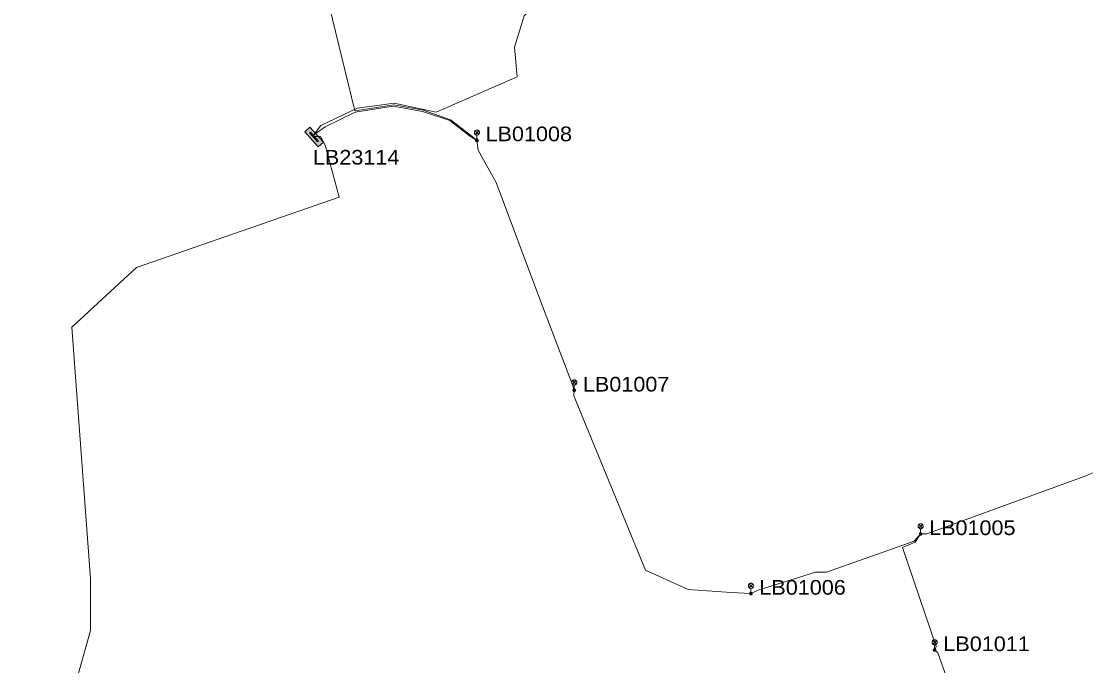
# Model space of a CAD drawing. Extents: x -688049 to -687261, y -973611 to -973038.
# Drawn here: x -687423.8 to -687265.6, y -973324.5 to -973229.3 of the extents above; entities that cross this region are included whole.
import ezdxf

# ---------------------------------------------------------------- set-up
doc = ezdxf.new("R2010")
doc.units = 0
doc.header["$LTSCALE"] = 0.87
doc.layers.add('1', color=7, linetype='Continuous', lineweight=13)

msp = doc.modelspace()

# ---------------------------------------------------------------- hatches: boundary and pattern name
at = {"layer": '1'}
for points in [[(-687379.952, -973247.823), (-687381.968, -973245.601), (-687381.227, -973244.929), (-687379.211, -973247.151)], [(-687380.059, -973247.109), (-687381.268, -973245.776), (-687381.12, -973245.642), (-687379.911, -973246.975)]]:
    msp.add_hatch(color=256, dxfattribs=at).paths.add_polyline_path(points)

# ---------------------------------------------------------------- linework, layer by layer
for p, q in [((-687356.805, -973245.455), (-687356.275, -973245.985)), ((-687356.805, -973245.985), (-687356.275, -973245.455)), ((-687356.54, -973246.87), (-687356.54, -973246.095)), ((-687342.425, -973282.375), (-687341.895, -973282.905)), ((-687342.425, -973282.905), (-687341.895, -973282.375)), ((-687291.275, -973303.625), (-687290.745, -973304.155)), ((-687291.275, -973304.155), (-687290.745, -973303.625)), ((-687291.01, -973305.04), (-687291.01, -973304.265)), ((-687316.335, -973312.435), (-687315.805, -973312.965)), ((-687316.335, -973312.965), (-687315.805, -973312.435)), ((-687289.215, -973320.775), (-687288.685, -973321.305)), ((-687289.215, -973321.305), (-687288.685, -973320.775)), ((-687288.95, -973322.19), (-687288.95, -973321.415))]:
    msp.add_line(p, q, dxfattribs=at)
for points in [[(-687356.54, -973246.87), (-687357.499, -973246.115), (-687360.447, -973243.857), (-687364.449, -973242.409), (-687368.798, -973241.637), (-687374.546, -973242.515), (-687382.562, -973209.507), (-687381.261, -973209.073), (-687380.24, -973207.97), (-687379.671, -973205.153), (-687381.293, -973203.137), (-687381.75, -973202.33)], [(-687350.83, -973213.5), (-687350.83, -973214.75), (-687347.414, -973226.104), (-687349.576, -973228.47), (-687350.998, -973233.095), (-687350.592, -973237.466), (-687362.557, -973242.691), (-687368.775, -973241.359), (-687374.206, -973242.131), (-687379.571, -973244.67), (-687380.798, -973246.294)], [(-687356.54, -973246.87), (-687357.651, -973246.213), (-687360.537, -973243.936), (-687364.573, -973242.598), (-687368.892, -973241.832), (-687374.497, -973242.717), (-687378.935, -973244.864), (-687380.483, -973245.949), (-687380.798, -973246.294)], [(-687380.798, -973246.294), (-687379.608, -973246.294), (-687378.955, -973247.562), (-687376.887, -973255.287), (-687406.818, -973265.671), (-687416.352, -973274.485), (-687413.576, -973311.675), (-687413.576, -973319.312), (-687415.981, -973327.719), (-687423.796, -973339.13), (-687419.572, -973351.385), (-687409.434, -973351.385), (-687402.464, -973355.4), (-687399.787, -973359.445), (-687396.201, -973367.518), (-687384.836, -973404.179), (-687376.008, -973424.395), (-687374.353, -973427.776), (-687369.362, -973427.776), (-687366.818, -973426.737), (-687366.538, -973425.138)], [(-687356.54, -973246.87), (-687356.347, -973248.305), (-687355.541, -973249.752), (-687353.676, -973253.1), (-687347.241, -973270.349), (-687342.401, -973283), (-687342.16, -973283.79), (-687342.16, -973283.015)], [(-687342.16, -973283.79), (-687342.227, -973284.618), (-687331.633, -973310.364), (-687325.353, -973313.26), (-687318.994, -973313.706), (-687316.07, -973313.85), (-687316.07, -973313.075)], [(-687291.01, -973305.04), (-687290.095, -973305.04), (-687266.448, -973296.412), (-687265.62, -973296)], [(-687316.07, -973313.85), (-687315.003, -973313.354), (-687306.515, -973310.665), (-687304.901, -973310.665), (-687291.976, -973306.105), (-687291.01, -973305.04)], [(-687291.01, -973305.04), (-687291.832, -973306.235), (-687293.694, -973307.029), (-687288.717, -973321.646), (-687288.9, -973322.19)], [(-687288.9, -973322.19), (-687288.451, -973322.592), (-687278.691, -973350.089), (-687278.75, -973350.656)]]:
    msp.add_lwpolyline(points, dxfattribs=at)
for points in [[(-687379.952, -973247.823), (-687381.968, -973245.601), (-687381.227, -973244.929), (-687379.211, -973247.151)], [(-687379.952, -973247.823), (-687381.968, -973245.601), (-687381.227, -973244.929), (-687379.211, -973247.151)], [(-687380.059, -973247.109), (-687381.268, -973245.776), (-687381.12, -973245.642), (-687379.911, -973246.975)], [(-687356.165, -973245.72), (-687356.171, -973245.655), (-687356.188, -973245.592), (-687356.215, -973245.533), (-687356.253, -973245.479), (-687356.299, -973245.433), (-687356.352, -973245.395), (-687356.412, -973245.368), (-687356.475, -973245.351), (-687356.54, -973245.345), (-687356.605, -973245.351), (-687356.668, -973245.368), (-687356.728, -973245.395), (-687356.781, -973245.433), (-687356.827, -973245.479), (-687356.865, -973245.533), (-687356.892, -973245.592), (-687356.909, -973245.655), (-687356.915, -973245.72), (-687356.909, -973245.785), (-687356.892, -973245.848), (-687356.865, -973245.908), (-687356.827, -973245.961), (-687356.781, -973246.007), (-687356.728, -973246.045), (-687356.668, -973246.072), (-687356.605, -973246.089), (-687356.54, -973246.095), (-687356.475, -973246.089), (-687356.412, -973246.072), (-687356.352, -973246.045), (-687356.299, -973246.007), (-687356.253, -973245.961), (-687356.215, -973245.908), (-687356.188, -973245.848), (-687356.171, -973245.785)], [(-687356.35, -973246.87), (-687356.353, -973246.837), (-687356.361, -973246.805), (-687356.375, -973246.775), (-687356.394, -973246.748), (-687356.418, -973246.724), (-687356.445, -973246.705), (-687356.475, -973246.691), (-687356.507, -973246.683), (-687356.54, -973246.68), (-687356.573, -973246.683), (-687356.605, -973246.691), (-687356.635, -973246.705), (-687356.662, -973246.724), (-687356.686, -973246.748), (-687356.705, -973246.775), (-687356.719, -973246.805), (-687356.727, -973246.837), (-687356.73, -973246.87), (-687356.727, -973246.903), (-687356.719, -973246.935), (-687356.705, -973246.965), (-687356.686, -973246.992), (-687356.662, -973247.016), (-687356.635, -973247.035), (-687356.605, -973247.049), (-687356.573, -973247.057), (-687356.54, -973247.06), (-687356.507, -973247.057), (-687356.475, -973247.049), (-687356.445, -973247.035), (-687356.418, -973247.016), (-687356.394, -973246.992), (-687356.375, -973246.965), (-687356.361, -973246.935), (-687356.353, -973246.903)], [(-687356.49, -973246.87), (-687356.491, -973246.861), (-687356.493, -973246.853), (-687356.497, -973246.845), (-687356.502, -973246.838), (-687356.508, -973246.832), (-687356.515, -973246.827), (-687356.523, -973246.823), (-687356.531, -973246.821), (-687356.54, -973246.82), (-687356.549, -973246.821), (-687356.557, -973246.823), (-687356.565, -973246.827), (-687356.572, -973246.832), (-687356.578, -973246.838), (-687356.583, -973246.845), (-687356.587, -973246.853), (-687356.589, -973246.861), (-687356.59, -973246.87), (-687356.589, -973246.879), (-687356.587, -973246.887), (-687356.583, -973246.895), (-687356.578, -973246.902), (-687356.572, -973246.908), (-687356.565, -973246.913), (-687356.557, -973246.917), (-687356.549, -973246.919), (-687356.54, -973246.92), (-687356.531, -973246.919), (-687356.523, -973246.917), (-687356.515, -973246.913), (-687356.508, -973246.908), (-687356.502, -973246.902), (-687356.497, -973246.895), (-687356.493, -973246.887), (-687356.491, -973246.879)], [(-687341.785, -973282.64), (-687341.791, -973282.575), (-687341.808, -973282.512), (-687341.835, -973282.452), (-687341.873, -973282.399), (-687341.919, -973282.353), (-687341.972, -973282.315), (-687342.032, -973282.288), (-687342.095, -973282.271), (-687342.16, -973282.265), (-687342.225, -973282.271), (-687342.288, -973282.288), (-687342.348, -973282.315), (-687342.401, -973282.353), (-687342.447, -973282.399), (-687342.485, -973282.452), (-687342.512, -973282.512), (-687342.529, -973282.575), (-687342.535, -973282.64), (-687342.529, -973282.705), (-687342.512, -973282.768), (-687342.485, -973282.828), (-687342.447, -973282.881), (-687342.401, -973282.927), (-687342.348, -973282.965), (-687342.288, -973282.992), (-687342.225, -973283.009), (-687342.16, -973283.015), (-687342.095, -973283.009), (-687342.032, -973282.992), (-687341.972, -973282.965), (-687341.919, -973282.927), (-687341.873, -973282.881), (-687341.835, -973282.828), (-687341.808, -973282.768), (-687341.791, -973282.705)], [(-687341.97, -973283.79), (-687341.973, -973283.757), (-687341.981, -973283.725), (-687341.995, -973283.695), (-687342.014, -973283.668), (-687342.038, -973283.644), (-687342.065, -973283.625), (-687342.095, -973283.611), (-687342.127, -973283.603), (-687342.16, -973283.6), (-687342.193, -973283.603), (-687342.225, -973283.611), (-687342.255, -973283.625), (-687342.282, -973283.644), (-687342.306, -973283.668), (-687342.325, -973283.695), (-687342.339, -973283.725), (-687342.347, -973283.757), (-687342.35, -973283.79), (-687342.347, -973283.823), (-687342.339, -973283.855), (-687342.325, -973283.885), (-687342.306, -973283.912), (-687342.282, -973283.936), (-687342.255, -973283.955), (-687342.225, -973283.969), (-687342.193, -973283.977), (-687342.16, -973283.98), (-687342.127, -973283.977), (-687342.095, -973283.969), (-687342.065, -973283.955), (-687342.038, -973283.936), (-687342.014, -973283.912), (-687341.995, -973283.885), (-687341.981, -973283.855), (-687341.973, -973283.823)], [(-687342.11, -973283.79), (-687342.111, -973283.781), (-687342.113, -973283.773), (-687342.117, -973283.765), (-687342.122, -973283.758), (-687342.128, -973283.752), (-687342.135, -973283.747), (-687342.143, -973283.743), (-687342.151, -973283.741), (-687342.16, -973283.74), (-687342.169, -973283.741), (-687342.177, -973283.743), (-687342.185, -973283.747), (-687342.192, -973283.752), (-687342.198, -973283.758), (-687342.203, -973283.765), (-687342.207, -973283.773), (-687342.209, -973283.781), (-687342.21, -973283.79), (-687342.209, -973283.799), (-687342.207, -973283.807), (-687342.203, -973283.815), (-687342.198, -973283.822), (-687342.192, -973283.828), (-687342.185, -973283.833), (-687342.177, -973283.837), (-687342.169, -973283.839), (-687342.16, -973283.84), (-687342.151, -973283.839), (-687342.143, -973283.837), (-687342.135, -973283.833), (-687342.128, -973283.828), (-687342.122, -973283.822), (-687342.117, -973283.815), (-687342.113, -973283.807), (-687342.111, -973283.799)], [(-687290.635, -973303.89), (-687290.641, -973303.825), (-687290.658, -973303.762), (-687290.685, -973303.702), (-687290.723, -973303.649), (-687290.769, -973303.603), (-687290.822, -973303.565), (-687290.882, -973303.538), (-687290.945, -973303.521), (-687291.01, -973303.515), (-687291.075, -973303.521), (-687291.138, -973303.538), (-687291.198, -973303.565), (-687291.251, -973303.603), (-687291.297, -973303.649), (-687291.335, -973303.702), (-687291.362, -973303.762), (-687291.379, -973303.825), (-687291.385, -973303.89), (-687291.379, -973303.955), (-687291.362, -973304.018), (-687291.335, -973304.078), (-687291.297, -973304.131), (-687291.251, -973304.177), (-687291.198, -973304.215), (-687291.138, -973304.242), (-687291.075, -973304.259), (-687291.01, -973304.265), (-687290.945, -973304.259), (-687290.882, -973304.242), (-687290.822, -973304.215), (-687290.769, -973304.177), (-687290.723, -973304.131), (-687290.685, -973304.078), (-687290.658, -973304.018), (-687290.641, -973303.955)], [(-687290.82, -973305.04), (-687290.823, -973305.007), (-687290.831, -973304.975), (-687290.845, -973304.945), (-687290.864, -973304.918), (-687290.888, -973304.894), (-687290.915, -973304.875), (-687290.945, -973304.861), (-687290.977, -973304.853), (-687291.01, -973304.85), (-687291.043, -973304.853), (-687291.075, -973304.861), (-687291.105, -973304.875), (-687291.132, -973304.894), (-687291.156, -973304.918), (-687291.175, -973304.945), (-687291.189, -973304.975), (-687291.197, -973305.007), (-687291.2, -973305.04), (-687291.197, -973305.073), (-687291.189, -973305.105), (-687291.175, -973305.135), (-687291.156, -973305.162), (-687291.132, -973305.186), (-687291.105, -973305.205), (-687291.075, -973305.219), (-687291.043, -973305.227), (-687291.01, -973305.23), (-687290.977, -973305.227), (-687290.945, -973305.219), (-687290.915, -973305.205), (-687290.888, -973305.186), (-687290.864, -973305.162), (-687290.845, -973305.135), (-687290.831, -973305.105), (-687290.823, -973305.073)], [(-687290.96, -973305.04), (-687290.961, -973305.031), (-687290.963, -973305.023), (-687290.967, -973305.015), (-687290.972, -973305.008), (-687290.978, -973305.002), (-687290.985, -973304.997), (-687290.993, -973304.993), (-687291.001, -973304.991), (-687291.01, -973304.99), (-687291.019, -973304.991), (-687291.027, -973304.993), (-687291.035, -973304.997), (-687291.042, -973305.002), (-687291.048, -973305.008), (-687291.053, -973305.015), (-687291.057, -973305.023), (-687291.059, -973305.031), (-687291.06, -973305.04), (-687291.059, -973305.049), (-687291.057, -973305.057), (-687291.053, -973305.065), (-687291.048, -973305.072), (-687291.042, -973305.078), (-687291.035, -973305.083), (-687291.027, -973305.087), (-687291.019, -973305.089), (-687291.01, -973305.09), (-687291.001, -973305.089), (-687290.993, -973305.087), (-687290.985, -973305.083), (-687290.978, -973305.078), (-687290.972, -973305.072), (-687290.967, -973305.065), (-687290.963, -973305.057), (-687290.961, -973305.049)], [(-687315.695, -973312.7), (-687315.701, -973312.635), (-687315.718, -973312.572), (-687315.745, -973312.513), (-687315.783, -973312.459), (-687315.829, -973312.413), (-687315.883, -973312.375), (-687315.942, -973312.348), (-687316.005, -973312.331), (-687316.07, -973312.325), (-687316.135, -973312.331), (-687316.198, -973312.348), (-687316.258, -973312.375), (-687316.311, -973312.413), (-687316.357, -973312.459), (-687316.395, -973312.513), (-687316.422, -973312.572), (-687316.439, -973312.635), (-687316.445, -973312.7), (-687316.439, -973312.765), (-687316.422, -973312.828), (-687316.395, -973312.888), (-687316.357, -973312.941), (-687316.311, -973312.987), (-687316.258, -973313.025), (-687316.198, -973313.052), (-687316.135, -973313.069), (-687316.07, -973313.075), (-687316.005, -973313.069), (-687315.942, -973313.052), (-687315.883, -973313.025), (-687315.829, -973312.987), (-687315.783, -973312.941), (-687315.745, -973312.888), (-687315.718, -973312.828), (-687315.701, -973312.765)], [(-687315.88, -973313.85), (-687315.883, -973313.817), (-687315.891, -973313.785), (-687315.905, -973313.755), (-687315.924, -973313.728), (-687315.948, -973313.704), (-687315.975, -973313.685), (-687316.005, -973313.671), (-687316.037, -973313.663), (-687316.07, -973313.66), (-687316.103, -973313.663), (-687316.135, -973313.671), (-687316.165, -973313.685), (-687316.192, -973313.704), (-687316.216, -973313.728), (-687316.235, -973313.755), (-687316.249, -973313.785), (-687316.257, -973313.817), (-687316.26, -973313.85), (-687316.257, -973313.883), (-687316.249, -973313.915), (-687316.235, -973313.945), (-687316.216, -973313.972), (-687316.192, -973313.996), (-687316.165, -973314.015), (-687316.135, -973314.029), (-687316.103, -973314.037), (-687316.07, -973314.04), (-687316.037, -973314.037), (-687316.005, -973314.029), (-687315.975, -973314.015), (-687315.948, -973313.996), (-687315.924, -973313.972), (-687315.905, -973313.945), (-687315.891, -973313.915), (-687315.883, -973313.883)], [(-687316.02, -973313.85), (-687316.021, -973313.841), (-687316.023, -973313.833), (-687316.027, -973313.825), (-687316.032, -973313.818), (-687316.038, -973313.812), (-687316.045, -973313.807), (-687316.053, -973313.803), (-687316.061, -973313.801), (-687316.07, -973313.8), (-687316.079, -973313.801), (-687316.087, -973313.803), (-687316.095, -973313.807), (-687316.102, -973313.812), (-687316.108, -973313.818), (-687316.113, -973313.825), (-687316.117, -973313.833), (-687316.119, -973313.841), (-687316.12, -973313.85), (-687316.119, -973313.859), (-687316.117, -973313.867), (-687316.113, -973313.875), (-687316.108, -973313.882), (-687316.102, -973313.888), (-687316.095, -973313.893), (-687316.087, -973313.897), (-687316.079, -973313.899), (-687316.07, -973313.9), (-687316.061, -973313.899), (-687316.053, -973313.897), (-687316.045, -973313.893), (-687316.038, -973313.888), (-687316.032, -973313.882), (-687316.027, -973313.875), (-687316.023, -973313.867), (-687316.021, -973313.859)], [(-687288.575, -973321.04), (-687288.581, -973320.975), (-687288.598, -973320.912), (-687288.625, -973320.852), (-687288.663, -973320.799), (-687288.709, -973320.753), (-687288.763, -973320.715), (-687288.822, -973320.688), (-687288.885, -973320.671), (-687288.95, -973320.665), (-687289.015, -973320.671), (-687289.078, -973320.688), (-687289.138, -973320.715), (-687289.191, -973320.753), (-687289.237, -973320.799), (-687289.275, -973320.852), (-687289.302, -973320.912), (-687289.319, -973320.975), (-687289.325, -973321.04), (-687289.319, -973321.105), (-687289.302, -973321.168), (-687289.275, -973321.227), (-687289.237, -973321.281), (-687289.191, -973321.327), (-687289.138, -973321.365), (-687289.078, -973321.392), (-687289.015, -973321.409), (-687288.95, -973321.415), (-687288.885, -973321.409), (-687288.822, -973321.392), (-687288.763, -973321.365), (-687288.709, -973321.327), (-687288.663, -973321.281), (-687288.625, -973321.227), (-687288.598, -973321.168), (-687288.581, -973321.105)], [(-687288.76, -973322.19), (-687288.763, -973322.157), (-687288.771, -973322.125), (-687288.785, -973322.095), (-687288.804, -973322.068), (-687288.828, -973322.044), (-687288.855, -973322.025), (-687288.885, -973322.011), (-687288.917, -973322.003), (-687288.95, -973322), (-687288.983, -973322.003), (-687289.015, -973322.011), (-687289.045, -973322.025), (-687289.072, -973322.044), (-687289.096, -973322.068), (-687289.115, -973322.095), (-687289.129, -973322.125), (-687289.137, -973322.157), (-687289.14, -973322.19), (-687289.137, -973322.223), (-687289.129, -973322.255), (-687289.115, -973322.285), (-687289.096, -973322.312), (-687289.072, -973322.336), (-687289.045, -973322.355), (-687289.015, -973322.369), (-687288.983, -973322.377), (-687288.95, -973322.38), (-687288.917, -973322.377), (-687288.885, -973322.369), (-687288.855, -973322.355), (-687288.828, -973322.336), (-687288.804, -973322.312), (-687288.785, -973322.285), (-687288.771, -973322.255), (-687288.763, -973322.223)], [(-687288.9, -973322.19), (-687288.901, -973322.181), (-687288.903, -973322.173), (-687288.907, -973322.165), (-687288.912, -973322.158), (-687288.918, -973322.152), (-687288.925, -973322.147), (-687288.933, -973322.143), (-687288.941, -973322.141), (-687288.95, -973322.14), (-687288.959, -973322.141), (-687288.967, -973322.143), (-687288.975, -973322.147), (-687288.982, -973322.152), (-687288.988, -973322.158), (-687288.993, -973322.165), (-687288.997, -973322.173), (-687288.999, -973322.181), (-687289, -973322.19), (-687288.999, -973322.199), (-687288.997, -973322.207), (-687288.993, -973322.215), (-687288.988, -973322.222), (-687288.982, -973322.228), (-687288.975, -973322.233), (-687288.967, -973322.237), (-687288.959, -973322.239), (-687288.95, -973322.24), (-687288.941, -973322.239), (-687288.933, -973322.237), (-687288.925, -973322.233), (-687288.918, -973322.228), (-687288.912, -973322.222), (-687288.907, -973322.215), (-687288.903, -973322.207), (-687288.901, -973322.199)]]:
    msp.add_lwpolyline(points, close=True, dxfattribs=at)

# ---------------------------------------------------------------- texts
at = {"layer": '1', "width": 1.1}
for s, height, p in [('LB01008', 2.167, (-687355.259, -973246.995)), ('LB23114', 2.168, (-687380.756, -973250.446)), ('LB01007', 2.167, (-687340.879, -973283.985)), ('LB01005', 2.167, (-687289.764, -973305.2)), ('LB01006', 2.167, (-687314.824, -973314.01)), ('LB01011', 2.167, (-687287.654, -973322.35))]:
    msp.add_text(s, height=height, dxfattribs=at).set_placement(p)

doc.saveas('drawing.dxf')
